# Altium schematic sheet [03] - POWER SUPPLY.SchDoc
size A4; DocumentNumber: 3; SheetNumber: 3; SheetTotal: 4
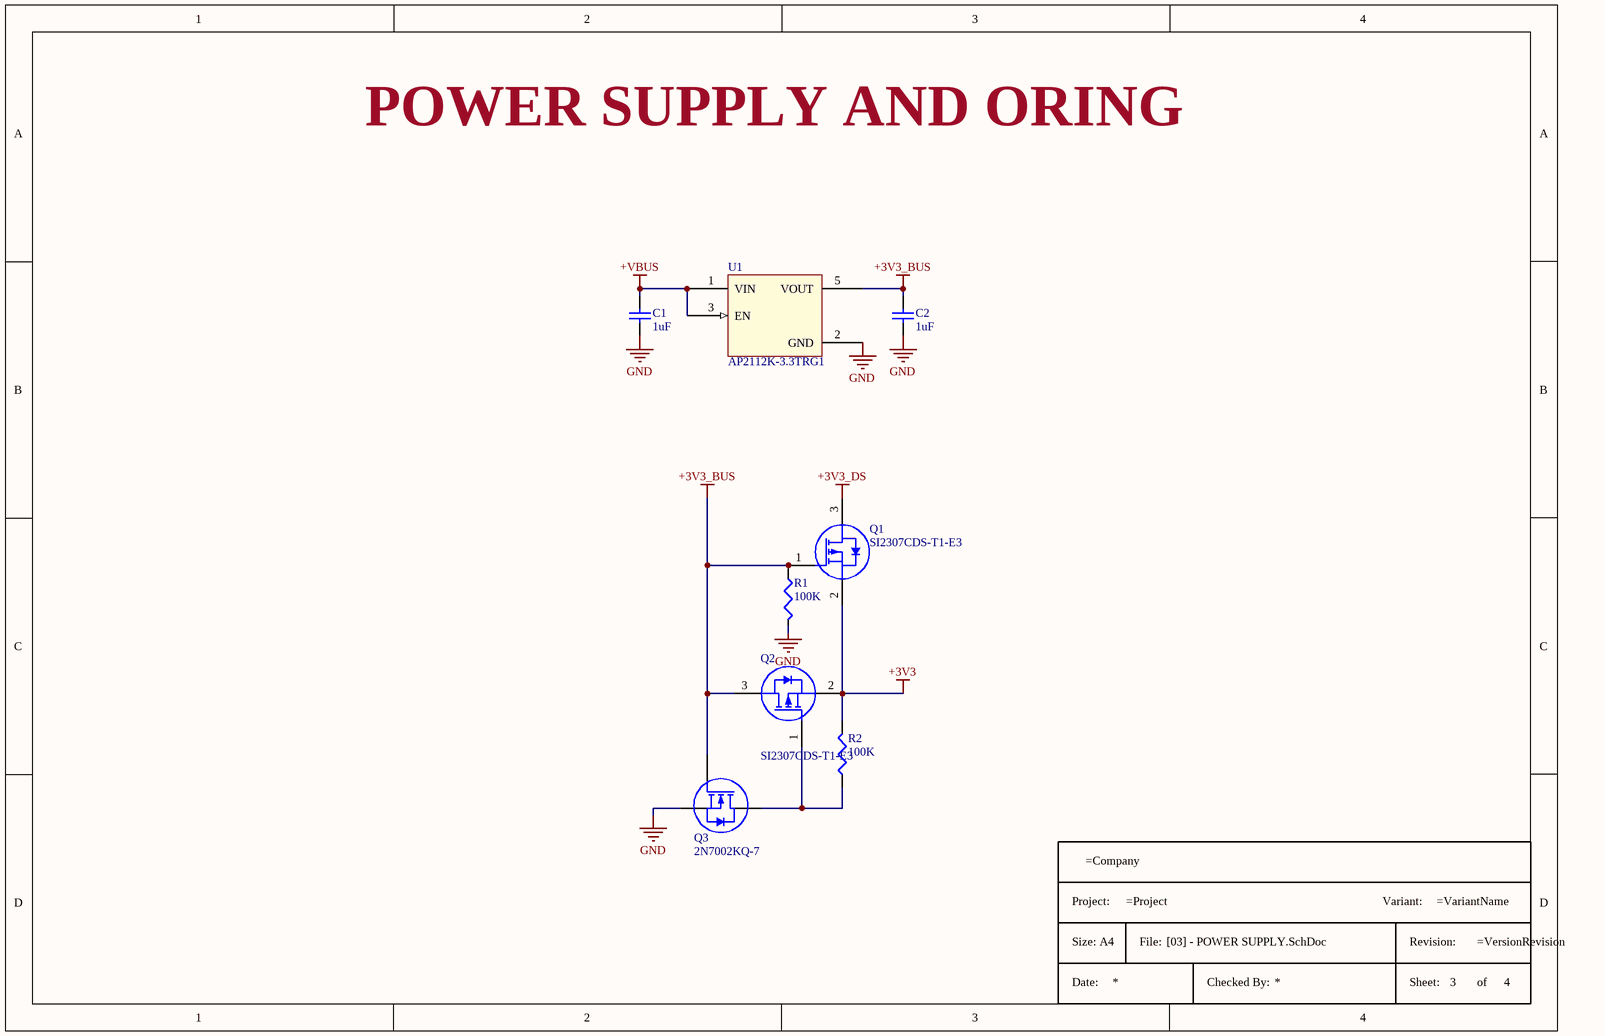
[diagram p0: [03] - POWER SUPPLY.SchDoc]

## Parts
*?  Title Block A4  (value not drawn)  (graphical)
C1  1uF  [C0402]
C2  1uF  [C0402]
Q1  SI2307CDS-T1-E3  [SOT-23_L2.9-W1.3-P1.90-LS2.4-BR]
Q2  SI2307CDS-T1-E3  [SOT-23_L2.9-W1.3-P1.90-LS2.4-BR]
Q3  2N7002KQ-7  [SOT-23_L2.9-W1.3-P1.90-LS2.4-BR]
R1  100K  [R0402]
R2  100K  [R0402]
U1  AP2112K-3.3TRG1  [SOT95P285X140-5N]

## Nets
+3V3: Q1.2(S) Q2.2(S) R2.2
+3V3_BUS: C2.2 Q1.1(G) Q2.3(D) Q3.1(G) R1.1 U1.5(VOUT)
+3V3_DS: Q1.3(D)
+VBUS: C1.2 U1.1(VIN) U1.3(EN)
GND: C1.1 C2.1 Q3.2(S) R1.2 U1.2(GND)
NetQ2_1: Q2.1(G) Q3.3(D) R2.1

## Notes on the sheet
- POWER SUPPLY AND ORING

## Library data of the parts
C1 C2 = C1005X5R1E105K050BC: TDK - C1005X5R1E105K050BC - COND, CERÁ MULT, X5R, 1UF, 25V, 0402; Dielectric Material: Ceramic; Tolerance: 10%
Q1 Q2 = SI2307CDS-T1-E3: P-Channel 30 V 3.5A (Tc) 1.1W (Ta), 1.8W (Tc) Surface Mount SOT-23-3 (TO-236); Number of Elements: 1; Package Body Material: Plastic; JEDEC-95 Code: TO-236AB; Transistor Application: SWITCHING; FET Technology: METAL-OXIDE SEMICONDUCTOR; Drain-source On Resistance-Max: 88mR; DS Breakdown Voltage-Min: 30V; Qualification Status: Not Qualified; Transistor Element Material: SILICON; Operating Mode: ENHANCEMENT MODE; Time @ Peak Reflow Temperature-Max (s): 30s
Q3 = 2N7002KQ-7: MOSFETs SOT-23; Manufacturer: Diodes Zetex; Rise Time: 3.4ns; Continuous Drain Current (ID): 380mA; Number of Elements: 1; Power Dissipation: 540mW; Turn-On Delay Time: 3.9ns; Turn-Off Delay Time: 15.7ns; Fall Time: 9.9ns; Gate to Source Voltage (Vgs): 20V
R1 R2 = CRCW0402100KFKED: RES SMD 100K OHM 1% 1/16W 0402; Manufacturer: Vishay; Resistance: 100kR; Temperature Coefficient: 100ppm/°C; Power Rating: 63mW; Voltage Rating: 50V
U1 = AP2112K-3.3TRG1: IC REG LDO 3.3V 0.6A SOT25; Manufacturer: Diodes; Min Input Voltage: 2.5V; Number of Outputs: 1; Dropout Voltage: 250mV; Max Input Voltage: 6V; Output Current: 600mA; Quiescent Current: 55uA; Polarity: Positive; Accuracy: 1.5%; Output Type: Fixed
